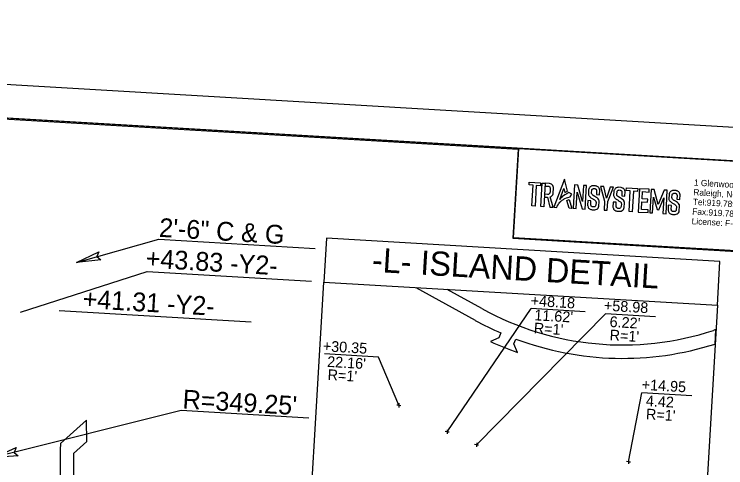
# Model space of a CAD drawing. Extents: x 2012744 to 2013625, y 444638 to 445237.
# Drawn here: x 2013223.7 to 2013488.7, y 445067.8 to 445236.8 of the extents above; entities that cross this region are included whole.
import ezdxf

# ---------------------------------------------------------------- set-up
doc = ezdxf.new("R2010")
doc.units = 0
for name, color, linetype in [('Old_Level_1', 7, 'Continuous'), ('Old_Level_10', 7, 'Continuous'), ('Old_Level_2', 7, 'Continuous'), ('Old_Level_58', 7, 'Continuous'), ('Prop Conc 4in Sidewalk', 7, 'Continuous'), ('Prop Dimension', 7, 'Continuous'), ('Prop Dimension Text', 7, 'Continuous'), ('Prop Shade Medium', 7, 'Continuous'), ('Prop Terminator CELL', 7, 'Continuous'), ('Sheet Clip Boundary CELL', 7, 'Continuous'), ('Sheet Plan And Profile CELL', 7, 'Continuous'), ('Sheet Plot Border Outside CELL', 7, 'Continuous')]:
    doc.layers.add(name, color=color, linetype=linetype)

msp = doc.modelspace()

# ---------------------------------------------------------------- linework, layer by layer
at = {"layer": 'Old_Level_1'}
for points in [[(2013415.55, 445174.17), (2013419.78, 445173.92), (2013419.72, 445172.88), (2013418.17, 445172.97), (2013417.72, 445165.28), (2013416.55, 445165.34), (2013417, 445173.09), (2013415.51, 445173.18)], [(2013420.36, 445173.88), (2013421.51, 445173.81), (2013421, 445165.04), (2013419.85, 445165.11)], [(2013421.45, 445172.77), (2013422.64, 445172.7), (2013422.79, 445172.67), (2013422.99, 445172.58), (2013423.14, 445172.46), (2013423.25, 445172.31), (2013423.32, 445172.15), (2013423.37, 445172.01), (2013423.36, 445171.72), (2013423.29, 445170.48), (2013423.25, 445170.32), (2013423.19, 445170.1), (2013423.12, 445169.96), (2013423.01, 445169.83), (2013422.87, 445169.73), (2013422.65, 445169.67), (2013422.49, 445169.66), (2013422.33, 445169.65), (2013421.27, 445169.7), (2013421.22, 445168.65), (2013422.27, 445168.59), (2013423.24, 445164.95), (2013424.45, 445164.89), (2013423.35, 445168.73), (2013423.54, 445168.79), (2013423.82, 445168.97), (2013424.08, 445169.22), (2013424.27, 445169.53), (2013424.4, 445169.84), (2013424.4, 445169.93), (2013424.55, 445172.21), (2013424.47, 445172.59), (2013424.31, 445172.94), (2013424.12, 445173.19), (2013423.78, 445173.44), (2013423.45, 445173.57), (2013423.12, 445173.71), (2013422.92, 445173.72), (2013421.51, 445173.81)], [(2013428.63, 445175.32), (2013424.67, 445164.87), (2013425.78, 445164.81), (2013425.98, 445165.22), (2013426.3, 445165.78), (2013426.47, 445166.09), (2013426.67, 445166.34), (2013426.96, 445166.71), (2013427.14, 445166.93), (2013427.34, 445167.11), (2013427.54, 445167.3), (2013427.8, 445167.53), (2013428.01, 445167.66), (2013428.23, 445167.81), (2013428.51, 445167.95), (2013428.77, 445168.08), (2013429.39, 445168.33), (2013429.9, 445168.5), (2013430.74, 445168.73), (2013431.37, 445169.77), (2013430.31, 445170.31), (2013429.47, 445169.92), (2013428.76, 445169.5), (2013428.24, 445169.14), (2013427.97, 445168.94), (2013427.69, 445168.67), (2013427.4, 445168.4), (2013427.19, 445168.2), (2013426.98, 445167.89), (2013426.87, 445167.72), (2013428.43, 445171.82), (2013428.84, 445170.35), (2013429.82, 445170.92)], [(2013432.39, 445173.19), (2013431.89, 445164.47), (2013433, 445164.41), (2013433.36, 445170.54), (2013435.22, 445164.27), (2013436.34, 445164.21), (2013436.85, 445172.95), (2013435.76, 445173.01), (2013435.41, 445167.03), (2013433.57, 445173.12)], [(2013440.55, 445169.62), (2013441.7, 445169.55), (2013441.8, 445171.29), (2013441.72, 445171.64), (2013441.6, 445171.95), (2013441.46, 445172.15), (2013441.29, 445172.34), (2013441.08, 445172.49), (2013440.87, 445172.59), (2013440.87, 445172.59), (2013440.65, 445172.7), (2013440.41, 445172.77), (2013440.25, 445172.82), (2013439.38, 445172.86), (2013439.11, 445172.83), (2013438.88, 445172.8), (2013438.64, 445172.7), (2013438.43, 445172.6), (2013438.23, 445172.47), (2013438.07, 445172.32), (2013437.93, 445172.15), (2013437.82, 445171.96), (2013437.68, 445171.62), (2013437.64, 445171.36), (2013437.54, 445169.78), (2013437.59, 445169.54), (2013437.69, 445169.29), (2013437.82, 445169.07), (2013437.96, 445168.91), (2013438.17, 445168.72), (2013438.39, 445168.54), (2013438.52, 445168.42), (2013438.76, 445168.29), (2013438.99, 445168.16), (2013439.18, 445168.03), (2013439.39, 445167.87), (2013439.65, 445167.72), (2013439.86, 445167.6), (2013440.06, 445167.43), (2013440.21, 445167.27), (2013440.33, 445167.15), (2013440.39, 445166.9), (2013440.43, 445166.75), (2013440.34, 445165.64), (2013440.25, 445165.4), (2013440.11, 445165.2), (2013439.94, 445165.06), (2013439.76, 445164.99), (2013439.59, 445164.97), (2013439.11, 445164.98), (2013438.95, 445165.04), (2013438.79, 445165.14), (2013438.63, 445165.25), (2013438.57, 445165.42), (2013438.51, 445165.59), (2013438.46, 445165.73), (2013438.53, 445167.28), (2013437.37, 445167.34), (2013437.28, 445165.49), (2013437.33, 445165.34), (2013437.44, 445164.9), (2013437.52, 445164.75), (2013437.64, 445164.59), (2013437.81, 445164.39), (2013437.96, 445164.28), (2013438.17, 445164.18), (2013438.25, 445164.14), (2013438.46, 445164.04), (2013438.72, 445164), (2013438.92, 445163.96), (2013439.99, 445163.93), (2013440.29, 445163.98), (2013440.71, 445164.14), (2013440.86, 445164.2), (2013441.19, 445164.58), (2013441.38, 445164.96), (2013441.48, 445165.31), (2013441.55, 445167.02), (2013441.56, 445167.25), (2013441.51, 445167.45), (2013441.42, 445167.63), (2013441.18, 445168.02), (2013440.84, 445168.32), (2013440.37, 445168.64), (2013440.01, 445168.88), (2013439.3, 445169.31), (2013438.94, 445169.61), (2013438.79, 445169.83), (2013438.76, 445169.97), (2013438.73, 445170.12), (2013438.83, 445171.33), (2013438.89, 445171.45), (2013438.96, 445171.58), (2013439.06, 445171.65), (2013439.18, 445171.74), (2013439.31, 445171.79), (2013439.44, 445171.83), (2013439.52, 445171.81), (2013439.53, 445171.85), (2013440, 445171.81), (2013440.14, 445171.75), (2013440.27, 445171.69), (2013440.41, 445171.63), (2013440.47, 445171.52), (2013440.55, 445171.38), (2013440.59, 445171.24), (2013440.63, 445171.1), (2013440.62, 445170.95)], [(2013443.36, 445172.55), (2013442.09, 445172.62), (2013443.58, 445167.08), (2013443.4, 445163.82), (2013444.59, 445163.75), (2013444.77, 445166.99), (2013446.92, 445172.36), (2013445.67, 445172.4), (2013444.27, 445168.3)], [(2013449.97, 445169.07), (2013451.12, 445169), (2013451.22, 445170.74), (2013451.14, 445171.1), (2013451.02, 445171.4), (2013450.88, 445171.6), (2013450.71, 445171.79), (2013450.5, 445171.94), (2013450.29, 445172.04), (2013450.29, 445172.04), (2013450.07, 445172.15), (2013449.83, 445172.23), (2013449.67, 445172.28), (2013448.8, 445172.31), (2013448.53, 445172.28), (2013448.3, 445172.26), (2013448.06, 445172.15), (2013447.85, 445172.06), (2013447.65, 445171.93), (2013447.49, 445171.78), (2013447.35, 445171.6), (2013447.25, 445171.41), (2013447.1, 445171.07), (2013447.06, 445170.82), (2013446.96, 445169.23), (2013447.01, 445168.99), (2013447.11, 445168.74), (2013447.24, 445168.53), (2013447.38, 445168.36), (2013447.59, 445168.18), (2013447.81, 445167.99), (2013447.94, 445167.87), (2013448.18, 445167.74), (2013448.41, 445167.62), (2013448.6, 445167.48), (2013448.81, 445167.32), (2013449.07, 445167.18), (2013449.28, 445167.05), (2013449.48, 445166.88), (2013449.63, 445166.73), (2013449.75, 445166.6), (2013449.81, 445166.36), (2013449.85, 445166.2), (2013449.76, 445165.09), (2013449.67, 445164.85), (2013449.54, 445164.65), (2013449.36, 445164.51), (2013449.18, 445164.44), (2013449.01, 445164.42), (2013448.53, 445164.44), (2013448.37, 445164.49), (2013448.21, 445164.6), (2013448.05, 445164.7), (2013447.99, 445164.88), (2013447.93, 445165.05), (2013447.88, 445165.18), (2013447.96, 445166.74), (2013446.79, 445166.79), (2013446.7, 445164.94), (2013446.75, 445164.8), (2013446.86, 445164.36), (2013446.94, 445164.21), (2013447.06, 445164.04), (2013447.23, 445163.84), (2013447.38, 445163.74), (2013447.59, 445163.63), (2013447.67, 445163.59), (2013447.88, 445163.49), (2013448.14, 445163.45), (2013448.34, 445163.42), (2013449.41, 445163.38), (2013449.71, 445163.44), (2013450.13, 445163.6), (2013450.28, 445163.65), (2013450.61, 445164.03), (2013450.8, 445164.41), (2013450.9, 445164.76), (2013450.97, 445166.47), (2013450.98, 445166.71), (2013450.93, 445166.9), (2013450.84, 445167.08), (2013450.6, 445167.48), (2013450.26, 445167.77), (2013449.79, 445168.09), (2013449.43, 445168.34), (2013448.72, 445168.76), (2013448.36, 445169.06), (2013448.21, 445169.28), (2013448.18, 445169.43), (2013448.15, 445169.57), (2013448.25, 445170.78), (2013448.31, 445170.91), (2013448.38, 445171.03), (2013448.48, 445171.1), (2013448.6, 445171.19), (2013448.73, 445171.24), (2013448.86, 445171.29), (2013448.94, 445171.27), (2013448.95, 445171.3), (2013449.42, 445171.27), (2013449.56, 445171.2), (2013449.69, 445171.14), (2013449.83, 445171.08), (2013449.89, 445170.98), (2013449.97, 445170.83), (2013450.01, 445170.69), (2013450.05, 445170.55), (2013450.04, 445170.4)], [(2013451.72, 445172.07), (2013455.95, 445171.82), (2013455.89, 445170.79), (2013454.34, 445170.88), (2013453.89, 445163.18), (2013452.72, 445163.25), (2013453.17, 445171), (2013451.68, 445171.08)], [(2013460.25, 445171.57), (2013456.56, 445171.78), (2013456.05, 445163.08), (2013459.78, 445162.87), (2013459.84, 445163.85), (2013457.32, 445164), (2013457.49, 445166.91), (2013459.6, 445166.79), (2013459.66, 445167.83), (2013457.53, 445167.95), (2013457.69, 445170.69), (2013460.19, 445170.55)], [(2013463.61, 445165.94), (2013462.03, 445171.5), (2013460.92, 445171.51), (2013460.45, 445162.79), (2013461.5, 445162.74), (2013461.82, 445168.57), (2013463.18, 445163.99), (2013463.85, 445163.93), (2013465.65, 445168.4), (2013465.33, 445162.54), (2013466.47, 445162.48), (2013466.95, 445171.18), (2013465.8, 445171.24)], [(2013470.5, 445167.88), (2013471.65, 445167.81), (2013471.75, 445169.55), (2013471.67, 445169.91), (2013471.55, 445170.21), (2013471.41, 445170.41), (2013471.24, 445170.6), (2013471.03, 445170.75), (2013470.82, 445170.85), (2013470.82, 445170.85), (2013470.6, 445170.96), (2013470.36, 445171.04), (2013470.2, 445171.09), (2013469.33, 445171.12), (2013469.06, 445171.09), (2013468.83, 445171.06), (2013468.59, 445170.96), (2013468.39, 445170.86), (2013468.18, 445170.73), (2013468.02, 445170.59), (2013467.89, 445170.41), (2013467.78, 445170.22), (2013467.63, 445169.88), (2013467.59, 445169.62), (2013467.5, 445168.04), (2013467.54, 445167.8), (2013467.64, 445167.55), (2013467.77, 445167.33), (2013467.91, 445167.17), (2013468.13, 445166.98), (2013468.34, 445166.8), (2013468.48, 445166.68), (2013468.71, 445166.55), (2013468.95, 445166.43), (2013469.13, 445166.29), (2013469.34, 445166.13), (2013469.6, 445165.98), (2013469.81, 445165.86), (2013470.01, 445165.69), (2013470.16, 445165.54), (2013470.28, 445165.41), (2013470.34, 445165.17), (2013470.38, 445165.01), (2013470.3, 445163.9), (2013470.2, 445163.66), (2013470.07, 445163.46), (2013469.89, 445163.32), (2013469.71, 445163.25), (2013469.54, 445163.23), (2013469.06, 445163.25), (2013468.9, 445163.3), (2013468.74, 445163.41), (2013468.58, 445163.51), (2013468.52, 445163.68), (2013468.46, 445163.86), (2013468.41, 445163.99), (2013468.49, 445165.55), (2013467.32, 445165.6), (2013467.23, 445163.75), (2013467.28, 445163.6), (2013467.39, 445163.17), (2013467.47, 445163.02), (2013467.59, 445162.85), (2013467.77, 445162.65), (2013467.91, 445162.55), (2013468.12, 445162.44), (2013468.2, 445162.4), (2013468.41, 445162.3), (2013468.68, 445162.26), (2013468.87, 445162.23), (2013469.94, 445162.19), (2013470.24, 445162.24), (2013470.66, 445162.41), (2013470.81, 445162.46), (2013471.14, 445162.84), (2013471.33, 445163.22), (2013471.43, 445163.57), (2013471.5, 445165.28), (2013471.51, 445165.52), (2013471.46, 445165.71), (2013471.37, 445165.89), (2013471.13, 445166.28), (2013470.79, 445166.58), (2013470.32, 445166.9), (2013469.96, 445167.14), (2013469.26, 445167.57), (2013468.89, 445167.87), (2013468.74, 445168.09), (2013468.71, 445168.24), (2013468.68, 445168.38), (2013468.78, 445169.59), (2013468.85, 445169.72), (2013468.92, 445169.84), (2013469.01, 445169.91), (2013469.13, 445170), (2013469.26, 445170.05), (2013469.4, 445170.09), (2013469.47, 445170.08), (2013469.48, 445170.11), (2013469.96, 445170.08), (2013470.09, 445170.01), (2013470.23, 445169.95), (2013470.36, 445169.89), (2013470.42, 445169.79), (2013470.5, 445169.64), (2013470.54, 445169.5), (2013470.58, 445169.36), (2013470.57, 445169.21)], [(2013429.47, 445167.41), (2013430.45, 445167.73), (2013431.39, 445164.45), (2013430.34, 445164.55)], [(2013339.03, 445136.98), (2013485.6, 445128.34), (2013486.56, 445144.66), (2013339.99, 445153.3)], [(2013339.03, 445136.98), (2013485.6, 445128.34), (2013478.02, 444999.85), (2013331.46, 445008.49)]]:
    msp.add_lwpolyline(points, close=True, dxfattribs=at)
at = {"layer": 'Old_Level_58'}
msp.add_lwpolyline([(2013411.6, 445186.8), (2013511.45, 445180.92), (2013509.49, 445147.63), (2013409.64, 445153.51)], close=True, dxfattribs=at)
at = {"layer": 'Prop Conc 4in Sidewalk'}
for radius, end in [(108.5, 288.1883), (113.5, 246.452)]:
    msp.add_arc((2013450.34, 445222.07), radius, 241.0711, end, dxfattribs=at)
at = {"layer": 'Prop Dimension'}
for p, q in [((2013246.92, 445144.31), (2013277.56, 445152.97)), ((2013277.56, 445152.97), (2013335.83, 445149.54)), ((2013225.97, 445125.8), (2013273.24, 445140.92)), ((2013273.24, 445140.92), (2013334.4, 445137.32)), ((2013240.45, 445126.37), (2013311.94, 445122.16)), ((2013384.95, 445081.23), (2013416.28, 445127.14)), ((2013443.89, 445125.17), (2013395.93, 445076.39)), ((2013436.37, 445125.95), (2013416.28, 445127.14)), ((2013462.51, 445124.08), (2013443.89, 445125.17)), ((2013359.34, 445109.04), (2013339.25, 445110.22)), ((2013366.94, 445091.07), (2013359.34, 445109.04)), ((2013452.51, 445070.04), (2013457.42, 445095.72)), ((2013476.04, 445094.62), (2013457.42, 445095.72)), ((2013285.84, 445089.12), (2013216.04, 445071.62)), ((2013333.38, 445086.31), (2013285.84, 445089.12))]:
    msp.add_line(p, q, dxfattribs=at)
at = {"layer": 'Prop Dimension Text'}
for p, q in [((2013366.94, 445091.07), (2013366.19, 445091.12)), ((2013366.98, 445091.82), (2013366.9, 445090.32)), ((2013366.94, 445091.07), (2013367.69, 445091.03)), ((2013384.95, 445081.23), (2013384.2, 445081.28)), ((2013384.99, 445081.98), (2013384.9, 445080.49)), ((2013384.95, 445081.23), (2013385.69, 445081.19)), ((2013395.93, 445076.39), (2013395.18, 445076.43)), ((2013395.97, 445077.14), (2013395.88, 445075.64)), ((2013395.93, 445076.39), (2013396.68, 445076.34)), ((2013452.51, 445070.04), (2013451.76, 445070.09)), ((2013452.55, 445070.79), (2013452.46, 445069.29)), ((2013452.51, 445070.04), (2013453.25, 445070))]:
    msp.add_line(p, q, dxfattribs=at)
at = {"layer": 'Prop Shade Medium'}
for p, q in [((2013373.34, 445134.95), (2013395.44, 445122.74)), ((2013397.86, 445127.11), (2013384.91, 445134.27)), ((2013405, 445118.03), (2013404.25, 445116.17)), ((2013484.75, 445113.91), (2013485.06, 445119.27)), ((2013404.25, 445116.17), (2013401.1, 445114.84)), ((2013409.81, 445113.92), (2013410.56, 445115.77)), ((2013411.14, 445110.78), (2013409.81, 445113.92)), ((2013250.65, 445085.49), (2013240.92, 445076.82)), ((2013250.72, 445077.55), (2013250.65, 445085.49)), ((2013245.83, 445073.13), (2013250.72, 445077.55))]:
    msp.add_line(p, q, dxfattribs=at)
for centre, radius, start, end in [((2013450.34, 445222.07), 108.5, 241.0711, 288.1883), ((2013450.34, 445222.07), 113.5, 241.0711, 246.452), ((2013943.84, 443720.07), 1472.5, 108.1535, 108.18835), ((2013450.34, 445222.07), 118, 245.3337, 250.5951), ((2013450.34, 445222.07), 113.5, 249.4809, 287.6441), ((2013514.28, 445067.92), 273.5, 178.1336, 185.9047), ((2013514.28, 445067.92), 268.5, 178.8864, 190.6549)]:
    msp.add_arc(centre, radius, start, end, dxfattribs=at)
at = {"layer": 'Prop Terminator CELL'}
for points in [[(2013256, 445145.27), (2013246.92, 445144.31), (2013255.2, 445148.31), (2013254.52, 445146.46)], [(2013225.14, 445072.31), (2013216.04, 445071.62), (2013224.43, 445075.37), (2013223.7, 445073.54)]]:
    msp.add_lwpolyline(points, close=True, dxfattribs=at)
at = {"layer": 'Sheet Clip Boundary CELL'}
for points in [[(2013605.95, 445084.18), (2013506.09, 445090.07), (2013509.49, 445147.63), (2013409.64, 445153.51), (2013411.6, 445186.8), (2012862.6, 445219.16), (2012831.71, 444695.07), (2013580.41, 444650.94)], [(2012832.37, 444695.56), (2012863.22, 445218.85), (2013411.41, 445186.54), (2013409.45, 445153.34), (2013509.31, 445147.45), (2013505.92, 445089.85), (2013605.86, 445083.96), (2013580.34, 444651.05)]]:
    msp.add_lwpolyline(points, close=True, dxfattribs=at)
at = {"layer": 'Sheet Plan And Profile CELL'}
msp.add_lwpolyline([(2013611.3, 445175.03), (2012862.6, 445219.16), (2012831.71, 444695.07), (2013580.41, 444650.94)], close=True, dxfattribs=at)
at = {"layer": 'Sheet Plot Border Outside CELL'}
msp.add_lwpolyline([(2012743.62, 444687.74), (2013592.15, 444637.73), (2013624.51, 445186.77), (2012775.99, 445236.79)], close=True, dxfattribs=at)

# ---------------------------------------------------------------- texts
at = {"layer": 'Old_Level_10'}
for s, p in [('+48.18', (2013415.98, 445128.13)), ('+58.98', (2013443.26, 445126.36)), ("11.62'", (2013417.34, 445122.76)), ("6.22'", (2013445.38, 445120.29)), ("R=1'", (2013417.15, 445117.91)), ("R=1'", (2013445.39, 445115.32)), ('+30.35', (2013338.55, 445111.24)), ("22.16'", (2013340.17, 445105.41)), ("R=1'", (2013340.33, 445100.53)), ('+14.95', (2013457.34, 445096.87)), ('4.42', (2013458.91, 445090.83)), ("R=1'", (2013458.92, 445085.86))]:
    msp.add_text(s, height=4, rotation=356.6264, dxfattribs=at).set_placement(p)
at = {"layer": 'Old_Level_2'}
for s, p in [('1 Glenwood Avenue', (2013476.82, 445172.96)), ('Raleigh, NC 27603', (2013476.61, 445169.37)), ('Tel:919.789.9977 ', (2013476.4, 445165.77)), ('Fax:919.789.9591', (2013476.18, 445162.18)), ('License: F-0453', (2013475.97, 445158.59))]:
    msp.add_text(s, height=2.3288, rotation=356.6264, dxfattribs=at).set_placement(p)
at = {"layer": 'Prop Dimension'}
msp.add_text('-L- ISLAND DETAIL', height=9, rotation=356.6264, dxfattribs=at).set_placement((2013356.78, 445140.86))
at = {"layer": 'Prop Dimension Text'}
for s, p in [('2\'-6" C & G', (2013277.51, 445153.87)), ('+43.83 -Y2-', (2013272.51, 445142.44)), ('+41.31 -Y2-', (2013249.03, 445127.35)), ("R=349.25'", (2013286.26, 445089.94))]:
    msp.add_text(s, height=7, rotation=356.6264, dxfattribs=at).set_placement(p)

doc.saveas('drawing.dxf')
